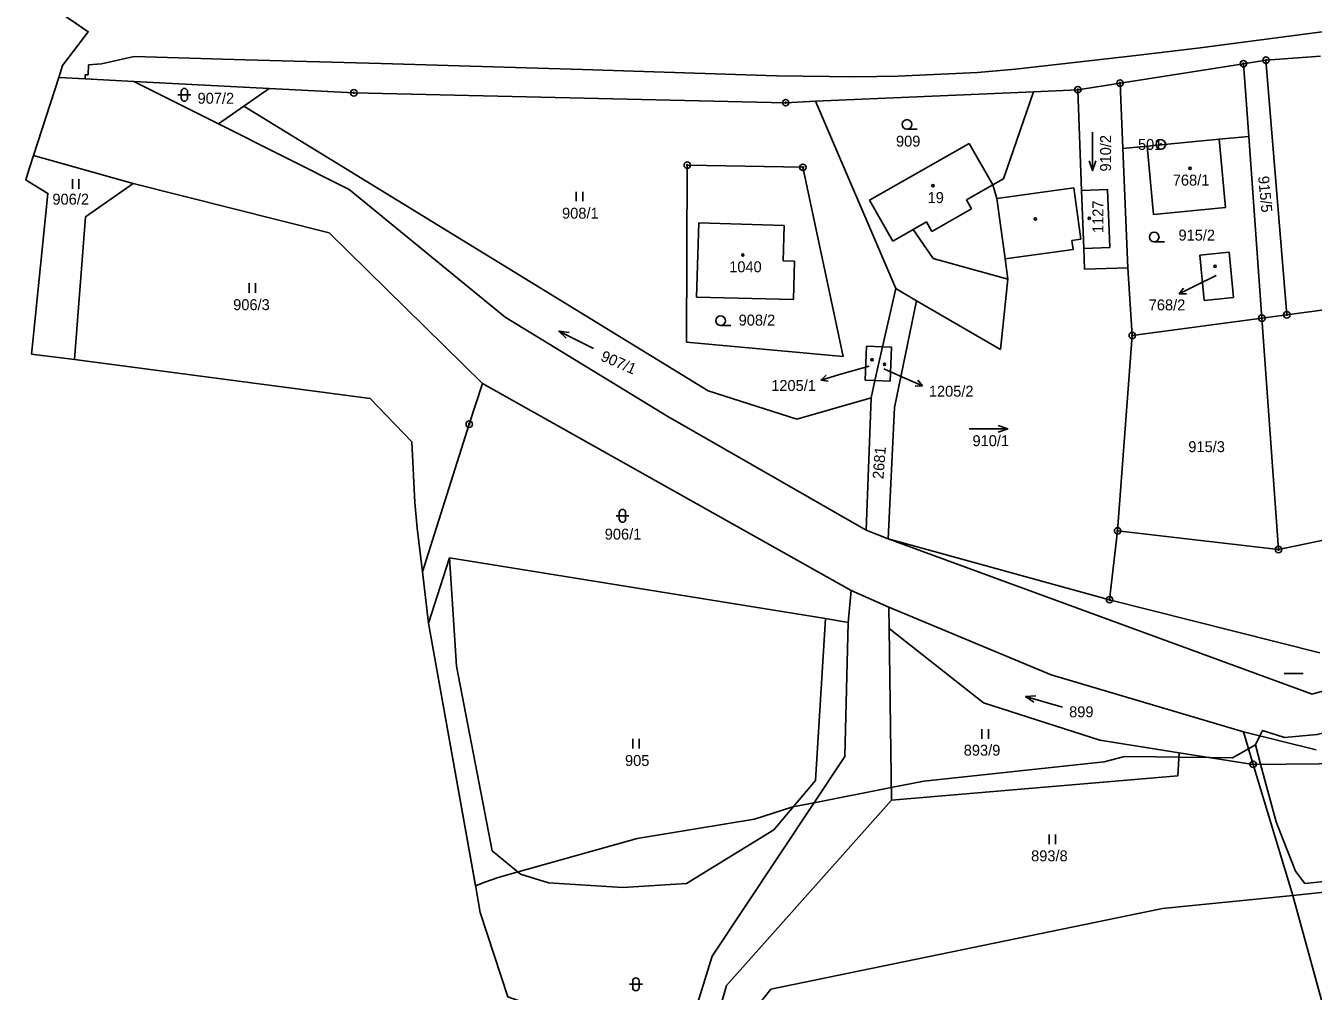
# Model space of a CAD drawing. Extents: x -439246 to -433691, y -1130252 to -1121148.
# Drawn here: x -438659.9 to -438459.6, y -1124542.5 to -1124392.3 of the extents above; entities that cross this region are included whole.
import ezdxf

# ---------------------------------------------------------------- set-up
doc = ezdxf.new("R2010")
doc.units = 0
for name, color, linetype in [('Vrstva 1', 7, 'Continuous'), ('Vrstva 13', 7, 'Continuous'), ('Vrstva 16', 7, 'Continuous'), ('Vrstva 17', 7, 'Continuous'), ('Vrstva 18', 7, 'Continuous'), ('Vrstva 19', 7, 'Continuous'), ('Vrstva 24', 7, 'Continuous'), ('Vrstva 25', 7, 'Continuous'), ('Vrstva 3', 7, 'Continuous'), ('Vrstva 37', 7, 'Continuous'), ('Vrstva 4', 7, 'Continuous'), ('Vrstva 52', 7, 'Continuous'), ('Vrstva 6', 7, 'Continuous')]:
    doc.layers.add(name, color=color, linetype=linetype)

msp = doc.modelspace()

# ---------------------------------------------------------------- linework, layer by layer
at = {"layer": 'Vrstva 1'}
for p, q in [((-438477.24, -1124395.72), (-438452.5, -1124392.47)), ((-438648.13, -1124398.21), (-438643.04, -1124397.1)), ((-438643.04, -1124397.1), (-438625.79, -1124397.57)), ((-438505.93, -1124399.07), (-438487.22, -1124396.92)), ((-438487.22, -1124396.92), (-438477.24, -1124395.72)), ((-438650.2, -1124399.93), (-438650.19, -1124398.35)), ((-438650.19, -1124398.35), (-438648.13, -1124398.21)), ((-438625.79, -1124397.57), (-438604.61, -1124398.17)), ((-438604.61, -1124398.17), (-438573.31, -1124399.08)), ((-438573.31, -1124399.08), (-438543.15, -1124400.06)), ((-438511.88, -1124399.58), (-438505.93, -1124399.07)), ((-438654.8, -1124400.32), (-438650.69, -1124400.54)), ((-438650.7, -1124399.94), (-438650.2, -1124399.93)), ((-438650.69, -1124400.54), (-438650.7, -1124399.94)), ((-438650.69, -1124400.54), (-438643.11, -1124400.94)), ((-438543.15, -1124400.06), (-438530.77, -1124400.22)), ((-438530.77, -1124400.22), (-438524.23, -1124400.15)), ((-438524.23, -1124400.15), (-438511.88, -1124399.58))]:
    msp.add_line(p, q, dxfattribs=at)
for points in [[(-438466.98, -1124397.65), (-438458.52, -1124397.04)], [(-438489.68, -1124401.21), (-438470.49, -1124398.2)], [(-438470.49, -1124398.2), (-438466.98, -1124397.65)], [(-438469.67, -1124409.51), (-438470.49, -1124398.2)], [(-438466.98, -1124397.65), (-438463.74, -1124437.27)], [(-438643.11, -1124400.94), (-438622.06, -1124402.04)], [(-438629.94, -1124407.54), (-438643.11, -1124400.94)], [(-438496.25, -1124402.24), (-438489.68, -1124401.21)], [(-438489.25, -1124411.39), (-438489.68, -1124401.21)], [(-438625.98, -1124404.78), (-438622.06, -1124402.04)], [(-438622.06, -1124402.04), (-438608.89, -1124402.73)], [(-438608.89, -1124402.73), (-438541.71, -1124404.26)], [(-438537.08, -1124404.05), (-438503.17, -1124402.55)], [(-438507.84, -1124416.11), (-438503.17, -1124402.55)], [(-438503.17, -1124402.55), (-438496.25, -1124402.24)], [(-438496.25, -1124402.24), (-438495.66, -1124417.93)], [(-438629.94, -1124407.54), (-438625.98, -1124404.78)], [(-438625.98, -1124404.78), (-438553.75, -1124449.12)], [(-438541.71, -1124404.26), (-438537.08, -1124404.05)], [(-438537.08, -1124404.05), (-438524.59, -1124433.18)], [(-438609.59, -1124417.76), (-438629.94, -1124407.54)], [(-438528.68, -1124419.42), (-438513.17, -1124410.63)], [(-438513.17, -1124410.63), (-438509.48, -1124417.05)], [(-438485.46, -1124411.03), (-438489.25, -1124411.39)], [(-438488.47, -1124429.94), (-438489.25, -1124411.39)], [(-438485.46, -1124411.03), (-438484.47, -1124421.64)], [(-438474.26, -1124409.95), (-438469.67, -1124409.51)], [(-438474.26, -1124409.95), (-438473.27, -1124420.56)], [(-438467.62, -1124437.79), (-438469.67, -1124409.51)], [(-438658.72, -1124412.5), (-438643.2, -1124416.82)], [(-438557.01, -1124413.98), (-438557.11, -1124441.53)], [(-438539.02, -1124414.32), (-438557.01, -1124413.98)], [(-438532.77, -1124443.78), (-438539.02, -1124414.32)], [(-438650.65, -1124422.02), (-438643.2, -1124416.82)], [(-438643.2, -1124416.82), (-438612.73, -1124424.49)], [(-438509.48, -1124417.05), (-438507.84, -1124416.11)], [(-438509.48, -1124417.05), (-438508.85, -1124419.15)], [(-438585.33, -1124437.65), (-438609.59, -1124417.76)], [(-438525.03, -1124425.81), (-438528.68, -1124419.42)], [(-438508.85, -1124419.15), (-438496.87, -1124417.52)], [(-438496.87, -1124417.52), (-438495.78, -1124425.51)], [(-438495.66, -1124417.93), (-438491.62, -1124417.78)], [(-438495.66, -1124417.93), (-438495.33, -1124426.94)], [(-438491.62, -1124417.78), (-438491.28, -1124426.79)], [(-438473.27, -1124420.56), (-438484.47, -1124421.64)], [(-438652.37, -1124444.25), (-438650.65, -1124422.02)], [(-438555.21, -1124422.96), (-438555.58, -1124434.54)], [(-438555.21, -1124422.96), (-438541.95, -1124423.35)], [(-438541.95, -1124423.35), (-438542.11, -1124428.87)], [(-438612.73, -1124424.49), (-438588.86, -1124447.94)], [(-438525.03, -1124425.81), (-438521.85, -1124423.99)], [(-438521.85, -1124423.99), (-438518.74, -1124428.53)], [(-438496.99, -1124427.11), (-438507.57, -1124428.55)], [(-438495.78, -1124425.51), (-438497.18, -1124425.71)], [(-438497.18, -1124425.71), (-438496.99, -1124427.11)], [(-438491.28, -1124426.79), (-438495.33, -1124426.94)], [(-438495.33, -1124426.94), (-438495.21, -1124430.19)], [(-438542.11, -1124428.87), (-438540.31, -1124428.91)], [(-438540.46, -1124434.91), (-438540.31, -1124428.91)], [(-438518.74, -1124428.53), (-438507.14, -1124431.7)], [(-438507.57, -1124428.55), (-438507.14, -1124431.7)], [(-438477.28, -1124427.98), (-438472.7, -1124427.54)], [(-438477.28, -1124427.98), (-438476.6, -1124435.02)], [(-438472.7, -1124427.54), (-438472.02, -1124434.58)], [(-438495.21, -1124430.19), (-438488.47, -1124429.94)], [(-438487.78, -1124440.5), (-438488.47, -1124429.94)], [(-438524.59, -1124433.18), (-438526.63, -1124442.26)], [(-438524.59, -1124433.18), (-438521.33, -1124435.07)], [(-438508.29, -1124442.65), (-438507.14, -1124431.7)], [(-438555.58, -1124434.54), (-438540.46, -1124434.91)], [(-438524.79, -1124451.69), (-438521.33, -1124435.07)], [(-438521.33, -1124435.07), (-438508.29, -1124442.65)], [(-438476.6, -1124435.02), (-438472.02, -1124434.58)], [(-438463.74, -1124437.27), (-438439.79, -1124434.06)], [(-438467.62, -1124437.79), (-438463.74, -1124437.27)], [(-438560.06, -1124453.08), (-438585.33, -1124437.65)], [(-438487.78, -1124440.5), (-438467.62, -1124437.79)], [(-438465.02, -1124473.8), (-438467.62, -1124437.79)], [(-438490.06, -1124470.89), (-438487.78, -1124440.5)], [(-438557.11, -1124441.53), (-438532.77, -1124443.78)], [(-438529.15, -1124442.16), (-438529.36, -1124447.43)], [(-438526.63, -1124442.26), (-438529.15, -1124442.16)], [(-438526.63, -1124442.26), (-438527.81, -1124447.49)], [(-438525.23, -1124442.32), (-438526.63, -1124442.26)], [(-438525.45, -1124447.58), (-438525.23, -1124442.32)], [(-438529.36, -1124447.43), (-438527.81, -1124447.49)], [(-438588.86, -1124447.94), (-438590.93, -1124454.28)], [(-438588.86, -1124447.94), (-438531.49, -1124480.15)], [(-438553.75, -1124449.12), (-438539.96, -1124453.49)], [(-438527.81, -1124447.49), (-438528.42, -1124450.17)], [(-438527.81, -1124447.49), (-438525.45, -1124447.58)], [(-438539.96, -1124453.49), (-438528.42, -1124450.17)], [(-438528.42, -1124450.17), (-438529.16, -1124470.76)], [(-438529.16, -1124470.76), (-438560.06, -1124453.08)], [(-438525.76, -1124472.11), (-438524.79, -1124451.69)], [(-438590.93, -1124454.28), (-438598.23, -1124477.26)], [(-438440.34, -1124468.63), (-438465.02, -1124473.8)], [(-438525.76, -1124472.11), (-438529.16, -1124470.76)], [(-438490.06, -1124470.89), (-438491.31, -1124481.6)], [(-438465.02, -1124473.8), (-438490.06, -1124470.89)], [(-438491.31, -1124481.6), (-438525.76, -1124472.11)], [(-438525.76, -1124472.11), (-438459.79, -1124496.3)], [(-438593.99, -1124475.08), (-438597.27, -1124485.26)], [(-438593.99, -1124475.08), (-438535.49, -1124484.54)], [(-438592.94, -1124491.93), (-438593.99, -1124475.08)], [(-438531.49, -1124480.15), (-438531.97, -1124485.13)], [(-438531.49, -1124480.15), (-438525.66, -1124482.78)], [(-438525.66, -1124482.78), (-438525.62, -1124486.07)], [(-438500.39, -1124493.28), (-438525.66, -1124482.78)], [(-438458.6, -1124489.87), (-438491.31, -1124481.6)], [(-438535.49, -1124484.54), (-438537.06, -1124509.71)], [(-438531.97, -1124485.13), (-438535.49, -1124484.54)], [(-438531.97, -1124485.13), (-438532.51, -1124506.02)], [(-438525.62, -1124486.07), (-438510.95, -1124497.65)], [(-438525.62, -1124486.07), (-438525.24, -1124512.78)], [(-438459.79, -1124496.3), (-438427.59, -1124487.07)], [(-438587.37, -1124520.7), (-438592.94, -1124491.93)], [(-438470.49, -1124502.17), (-438500.39, -1124493.28)], [(-438510.95, -1124497.65), (-438492.83, -1124503.47)], [(-438492.83, -1124503.47), (-438480.47, -1124505.41)], [(-438468.97, -1124507.22), (-438470.49, -1124502.17)], [(-438459.19, -1124504.96), (-438470.49, -1124502.17)], [(-438480.47, -1124505.41), (-438468.97, -1124507.22)], [(-438532.51, -1124506.02), (-438553.14, -1124537.06)], [(-438468.97, -1124507.22), (-438443.25, -1124506.97)], [(-438462.8, -1124527.62), (-438468.97, -1124507.22)], [(-438537.06, -1124509.71), (-438543.57, -1124517.4)], [(-438525.24, -1124512.78), (-438550.92, -1124541.65)], [(-438543.57, -1124517.4), (-438557.12, -1124525.75)], [(-438582.94, -1124524.29), (-438587.37, -1124520.7)], [(-438462.8, -1124527.62), (-438402.08, -1124521.17)], [(-438578.62, -1124525.68), (-438582.94, -1124524.29)], [(-438567.02, -1124526.4), (-438578.62, -1124525.68)], [(-438557.12, -1124525.75), (-438567.02, -1124526.4)], [(-438462.8, -1124527.62), (-438454.73, -1124557.12)], [(-438553.14, -1124537.06), (-438564.51, -1124573.74)], [(-438550.92, -1124541.65), (-438559.43, -1124571.34)]]:
    msp.add_lwpolyline(points, dxfattribs=at)
at = {"layer": 'Vrstva 13'}
for points in [[(-438654.31, -1124390.42), (-438650.2, -1124393.22)], [(-438654.21, -1124398.49), (-438650.2, -1124393.22)], [(-438654.21, -1124398.49), (-438654.8, -1124400.32)], [(-438654.8, -1124400.32), (-438658.72, -1124412.5)], [(-438658.72, -1124412.5), (-438659.38, -1124414.56)], [(-438659.38, -1124414.56), (-438659.93, -1124416.28)], [(-438659.93, -1124416.28), (-438659.46, -1124416.56)], [(-438656.47, -1124418.39), (-438659.46, -1124416.56)], [(-438656.47, -1124418.39), (-438658.78, -1124440.93)], [(-438658.78, -1124440.93), (-438659.03, -1124443.37)], [(-438659.03, -1124443.37), (-438652.37, -1124444.25)], [(-438652.37, -1124444.25), (-438606.34, -1124450.3)], [(-438606.34, -1124450.3), (-438599.86, -1124457.06)], [(-438599.86, -1124457.06), (-438599.4, -1124466.49)], [(-438599.4, -1124466.49), (-438599.05, -1124470.49)], [(-438599.05, -1124470.49), (-438598.23, -1124477.26)], [(-438598.23, -1124477.26), (-438597.27, -1124485.26)], [(-438597.27, -1124485.26), (-438589.92, -1124526.35)], [(-438589.92, -1124526.35), (-438589.22, -1124530.3)], [(-438589.22, -1124530.3), (-438584.94, -1124543.38)]]:
    msp.add_lwpolyline(points, dxfattribs=at)
at = {"layer": 'Vrstva 16'}
for p, q in [((-438477.79, -1124432.67), (-438480.47, -1124434.03)), ((-438533.32, -1124446.58), (-438536.2, -1124447.42)), ((-438523.18, -1124447.11), (-438520.43, -1124448.31))]:
    msp.add_line(p, q, dxfattribs=at)
for points in [[(-438474.75, -1124431.14), (-438477.79, -1124432.67)], [(-438479.35, -1124434.02), (-438480.47, -1124434.03), (-438479.8, -1124433.13)], [(-438528.72, -1124445.24), (-438533.32, -1124446.58)], [(-438535.1, -1124447.62), (-438536.2, -1124447.42), (-438535.38, -1124446.66)], [(-438526.43, -1124445.69), (-438523.18, -1124447.11)], [(-438521.15, -1124447.45), (-438520.43, -1124448.31), (-438521.55, -1124448.37)]]:
    msp.add_lwpolyline(points, dxfattribs=at)
at = {"layer": 'Vrstva 24'}
for centre, radius in [((-438466.98, -1124397.65), 0.5), ((-438470.49, -1124398.2), 0.5), ((-438470.49, -1124398.2), 0.1), ((-438466.98, -1124397.65), 0.1), ((-438489.68, -1124401.21), 0.5), ((-438489.68, -1124401.21), 0.1), ((-438608.89, -1124402.73), 0.5), ((-438608.89, -1124402.73), 0.1), ((-438496.25, -1124402.24), 0.5), ((-438496.25, -1124402.24), 0.1), ((-438541.71, -1124404.26), 0.5), ((-438541.71, -1124404.26), 0.1), ((-438483.33, -1124410.76), 0.75), ((-438483.33, -1124410.76), 0.1), ((-438557.01, -1124413.98), 0.5), ((-438557.01, -1124413.98), 0.1), ((-438539.02, -1124414.32), 0.5), ((-438539.02, -1124414.32), 0.1), ((-438467.62, -1124437.79), 0.5), ((-438463.74, -1124437.27), 0.5), ((-438463.74, -1124437.27), 0.1), ((-438467.62, -1124437.79), 0.1), ((-438487.78, -1124440.5), 0.5), ((-438487.78, -1124440.5), 0.1), ((-438590.93, -1124454.28), 0.5), ((-438590.93, -1124454.28), 0.1), ((-438490.06, -1124470.89), 0.5), ((-438490.06, -1124470.89), 0.1), ((-438465.02, -1124473.8), 0.5), ((-438465.02, -1124473.8), 0.1), ((-438491.31, -1124481.6), 0.5), ((-438491.31, -1124481.6), 0.1), ((-438468.97, -1124507.22), 0.5), ((-438468.97, -1124507.22), 0.1)]:
    msp.add_circle(centre, radius, dxfattribs=at)
at = {"layer": 'Vrstva 25'}
for p, q in [((-438636.25, -1124403.04), (-438634.25, -1124403.04)), ((-438635.75, -1124403.54), (-438635.75, -1124402.54)), ((-438634.75, -1124402.54), (-438634.75, -1124403.54)), ((-438522.82, -1124408.4), (-438521.22, -1124408.4)), ((-438652.66, -1124417.67), (-438652.66, -1124416.17)), ((-438651.66, -1124417.67), (-438651.66, -1124416.17)), ((-438574.28, -1124419.61), (-438574.28, -1124418.11)), ((-438573.28, -1124419.61), (-438573.28, -1124418.11)), ((-438484.37, -1124425.91), (-438482.77, -1124425.91)), ((-438625.19, -1124433.84), (-438625.19, -1124432.34)), ((-438624.19, -1124433.84), (-438624.19, -1124432.34)), ((-438551.83, -1124438.94), (-438550.23, -1124438.94)), ((-438568.1, -1124468.55), (-438566.1, -1124468.55)), ((-438567.6, -1124469.05), (-438567.6, -1124468.05)), ((-438566.6, -1124468.05), (-438566.6, -1124469.05)), ((-438464.17, -1124493.06), (-438461.17, -1124493.06)), ((-438565.5, -1124504.77), (-438565.5, -1124503.27)), ((-438564.5, -1124504.77), (-438564.5, -1124503.27)), ((-438511.16, -1124503.24), (-438511.16, -1124501.74)), ((-438510.16, -1124503.24), (-438510.16, -1124501.74)), ((-438500.71, -1124519.65), (-438500.71, -1124518.15)), ((-438499.71, -1124519.65), (-438499.71, -1124518.15)), ((-438566, -1124541.45), (-438564, -1124541.45)), ((-438565.5, -1124541.95), (-438565.5, -1124540.95)), ((-438564.5, -1124540.95), (-438564.5, -1124541.95))]:
    msp.add_line(p, q, dxfattribs=at)
for points in [[(-438493.97, -1124408.83), (-438493.97, -1124414.83), (-438493.47, -1124413.33)], [(-438493.97, -1124414.83), (-438494.47, -1124413.33)], [(-438571.61, -1124442.49), (-438576.97, -1124439.81), (-438575.86, -1124440.93)], [(-438576.97, -1124439.81), (-438575.41, -1124440.03)], [(-438513.16, -1124455.01), (-438507.16, -1124455.01), (-438508.66, -1124454.51)], [(-438507.16, -1124455.01), (-438508.66, -1124455.51)], [(-438504.38, -1124496.64), (-438502.8, -1124496.57)], [(-438498.62, -1124498.3), (-438504.38, -1124496.64), (-438503.08, -1124497.53)]]:
    msp.add_lwpolyline(points, dxfattribs=at)
for centre, radius in [((-438522.82, -1124407.65), 0.75), ((-438478.79, -1124414.46), 0.175), ((-438518.8, -1124417.18), 0.175), ((-438502.86, -1124422.35), 0.175), ((-438494.47, -1124422.27), 0.175), ((-438484.37, -1124425.16), 0.75), ((-438548.37, -1124427.95), 0.175), ((-438474.9, -1124429.73), 0.175), ((-438551.83, -1124438.19), 0.75), ((-438528.26, -1124444.27), 0.175), ((-438526.33, -1124444.97), 0.175)]:
    msp.add_circle(centre, radius, dxfattribs=at)
for centre, start, end in [((-438635.25, -1124402.54), 0, 180), ((-438635.25, -1124403.54), 180, 0), ((-438567.1, -1124468.05), 0, 180), ((-438567.1, -1124469.05), 180, 0), ((-438565, -1124540.95), 0, 180), ((-438565, -1124541.95), 180, 0)]:
    msp.add_arc(centre, 0.5, start, end, dxfattribs=at)
at = {"layer": 'Vrstva 3'}
for points in [[(-438528.68, -1124419.42), (-438513.17, -1124410.63)], [(-438513.17, -1124410.63), (-438509.48, -1124417.05)], [(-438474.26, -1124409.95), (-438485.46, -1124411.03)], [(-438485.46, -1124411.03), (-438484.47, -1124421.64)], [(-438474.26, -1124409.95), (-438473.27, -1124420.56)], [(-438509.48, -1124417.05), (-438513.57, -1124419.4)], [(-438525.03, -1124425.81), (-438528.68, -1124419.42)], [(-438513.57, -1124419.4), (-438512.77, -1124420.78)], [(-438495.66, -1124417.93), (-438491.62, -1124417.78)], [(-438495.66, -1124417.93), (-438495.33, -1124426.94)], [(-438491.62, -1124417.78), (-438491.28, -1124426.79)], [(-438512.77, -1124420.78), (-438518.94, -1124424.33)], [(-438473.27, -1124420.56), (-438484.47, -1124421.64)], [(-438555.21, -1124422.96), (-438555.58, -1124434.54)], [(-438555.21, -1124422.96), (-438541.95, -1124423.35)], [(-438541.95, -1124423.35), (-438542.11, -1124428.87)], [(-438521.85, -1124423.99), (-438519.8, -1124422.82)], [(-438518.94, -1124424.33), (-438519.8, -1124422.82)], [(-438525.03, -1124425.81), (-438521.85, -1124423.99)], [(-438491.28, -1124426.79), (-438495.33, -1124426.94)], [(-438542.11, -1124428.87), (-438540.31, -1124428.91)], [(-438540.46, -1124434.91), (-438540.31, -1124428.91)], [(-438477.28, -1124427.98), (-438472.7, -1124427.54)], [(-438477.28, -1124427.98), (-438476.6, -1124435.02)], [(-438472.7, -1124427.54), (-438472.02, -1124434.58)], [(-438555.58, -1124434.54), (-438540.46, -1124434.91)], [(-438476.6, -1124435.02), (-438472.02, -1124434.58)], [(-438529.15, -1124442.16), (-438529.36, -1124447.43)], [(-438526.63, -1124442.26), (-438529.15, -1124442.16)], [(-438525.23, -1124442.32), (-438526.63, -1124442.26)], [(-438525.45, -1124447.58), (-438525.23, -1124442.32)], [(-438529.36, -1124447.43), (-438527.81, -1124447.49)], [(-438527.81, -1124447.49), (-438525.45, -1124447.58)]]:
    msp.add_lwpolyline(points, dxfattribs=at)
at = {"layer": 'Vrstva 37'}
for centre in [(-438478.79, -1124414.46), (-438518.8, -1124417.18), (-438494.47, -1124422.27), (-438548.37, -1124427.95), (-438474.9, -1124429.73), (-438528.26, -1124444.27)]:
    msp.add_circle(centre, 0.175, dxfattribs=at)
at = {"layer": 'Vrstva 4'}
for points in [[(-438474.26, -1124409.95), (-438485.46, -1124411.03)], [(-438509.48, -1124417.05), (-438513.57, -1124419.4)], [(-438513.57, -1124419.4), (-438512.77, -1124420.78)], [(-438508.85, -1124419.15), (-438507.57, -1124428.55)], [(-438512.77, -1124420.78), (-438518.94, -1124424.33)], [(-438521.85, -1124423.99), (-438519.8, -1124422.82)], [(-438518.94, -1124424.33), (-438519.8, -1124422.82)]]:
    msp.add_lwpolyline(points, dxfattribs=at)
at = {"layer": 'Vrstva 52'}
for points in [[(-438589.96, -1124526.1), (-438597.27, -1124485.26), (-438598.23, -1124477.26), (-438599.05, -1124470.49), (-438599.4, -1124466.49), (-438599.86, -1124457.06), (-438606.34, -1124450.3), (-438652.37, -1124444.25), (-438659.03, -1124443.37), (-438658.78, -1124440.93), (-438656.47, -1124418.39), (-438659.46, -1124416.56), (-438659.93, -1124416.28), (-438659.38, -1124414.56), (-438658.72, -1124412.5), (-438654.8, -1124400.32), (-438654.21, -1124398.49), (-438653.69, -1124397.81), (-438652.49, -1124396.23), (-438650.2, -1124393.22), (-438652.74, -1124391.49)], [(-438468.62, -1124504.2), (-438467.93, -1124502.8), (-438467.51, -1124501.96), (-438464.11, -1124503.02), (-438459.01, -1124502.6), (-438452.21, -1124500.9), (-438444.99, -1124500.26), (-438433.09, -1124497.28), (-438427.99, -1124494.95), (-438418.22, -1124485.39), (-438412.93, -1124481.63), (-438412.45, -1124482.64), (-438406.39, -1124495.24), (-438404.94, -1124498.25)], [(-438404.94, -1124498.25), (-438396.12, -1124516.19), (-438395.36, -1124517.76), (-438394.87, -1124518.76), (-438397.03, -1124519.15), (-438407.59, -1124521.08), (-438410.15, -1124520.66), (-438440.74, -1124524.48), (-438448.39, -1124524.48), (-438460.92, -1124525.76), (-438462.41, -1124523.84), (-438464.3, -1124518.99), (-438465.39, -1124516.19), (-438467.81, -1124507.21), (-438468.62, -1124504.2)], [(-438468.62, -1124504.2), (-438469.06, -1124504.45), (-438469.69, -1124504.81), (-438472.19, -1124506.21), (-438475.67, -1124506.16), (-438480.51, -1124506.1), (-438484.15, -1124506.06), (-438488.97, -1124506), (-438492.16, -1124506.85), (-438520.2, -1124509.82), (-438525.27, -1124510.82), (-438537.28, -1124513.2), (-438540.58, -1124513.85), (-438546.55, -1124515.77), (-438564.82, -1124518.74), (-438583.33, -1124523.97), (-438586.41, -1124524.84), (-438588.51, -1124525.58), (-438589.96, -1124526.1)], [(-438565.21, -1124716.57), (-438576.35, -1124697.33), (-438579.78, -1124675.28), (-438581.05, -1124667.1), (-438581.51, -1124664.14), (-438576.07, -1124640.31), (-438575.4, -1124637.35), (-438574.27, -1124616.44), (-438573.2, -1124612.36), (-438572.45, -1124609.51), (-438573.18, -1124593.81), (-438573.26, -1124592.07), (-438573.74, -1124581.88), (-438570.23, -1124573.74), (-438568.82, -1124570.46), (-438572.02, -1124552.38), (-438573.4, -1124550.5), (-438576.34, -1124546.48), (-438584.94, -1124543.38), (-438589.22, -1124530.3), (-438589.92, -1124526.35), (-438589.96, -1124526.1)]]:
    msp.add_lwpolyline(points, dxfattribs=at)
at = {"layer": 'Vrstva 6'}
for points in [[(-438480.68, -1124509.03), (-438480.47, -1124505.41)], [(-438525.24, -1124512.78), (-438480.68, -1124509.03)], [(-438462.8, -1124527.62), (-438483.07, -1124529.67)], [(-438483.07, -1124529.67), (-438544, -1124542.2)], [(-438544, -1124542.2), (-438553.35, -1124553.97)]]:
    msp.add_lwpolyline(points, dxfattribs=at)

# ---------------------------------------------------------------- texts
at = {"layer": 'Vrstva 16'}
for s, p in [('768/2', (-438485.22, -1124436.58)), ('1205/1', (-438543.95, -1124449.12)), ('1205/2', (-438519.43, -1124450.01))]:
    msp.add_text(s, height=1.7, dxfattribs=at).set_placement(p)
at = {"layer": 'Vrstva 17'}
msp.add_text('501', height=1.7, dxfattribs=at).set_placement((-438486.89, -1124411.61))
at = {"layer": 'Vrstva 18'}
for s, p in [('907/2', (-438633.2, -1124404.42)), ('909', (-438524.54, -1124411.1)), ('906/2', (-438655.78, -1124420.13)), ('908/1', (-438576.49, -1124422.31)), ('915/2', (-438480.59, -1124425.72)), ('906/3', (-438627.66, -1124436.54)), ('908/2', (-438549.02, -1124438.94)), ('910/1', (-438512.64, -1124457.71)), ('915/3', (-438479.06, -1124458.64)), ('906/1', (-438569.85, -1124472.25)), ('899', (-438497.6, -1124499.9)), ('893/9', (-438514, -1124505.87)), ('905', (-438566.7, -1124507.47)), ('893/8', (-438503.52, -1124522.31))]:
    msp.add_text(s, height=1.7, dxfattribs=at).set_placement(p)
for s, rotation, p in [('910/2', 90, (-438491.08, -1124414.98)), ('915/5', 275.6107, (-438468.22, -1124415.75)), ('907/1', 336.4911, (-438570.63, -1124444.33)), ('2681', 85.4316, (-438526.5, -1124462.88))]:
    msp.add_text(s, height=1.7, rotation=rotation, dxfattribs=at).set_placement(p)
at = {"layer": 'Vrstva 19'}
for s, height, p in [('768/1', 1.7, (-438481.48, -1124417.16)), ('19', 1.7, (-438519.62, -1124419.88)), ('1040', 1.7, (-438550.49, -1124430.65)), ('768/2', 0.1, (-438474.98, -1124431.11)), ('1205/1', 0.1, (-438528.92, -1124445.24)), ('1205/2', 0.1, (-438526.64, -1124445.69))]:
    msp.add_text(s, height=height, dxfattribs=at).set_placement(p)
msp.add_text('1127', height=1.7, rotation=90, dxfattribs=at).set_placement((-438492.27, -1124424.54))

doc.saveas('drawing.dxf')
